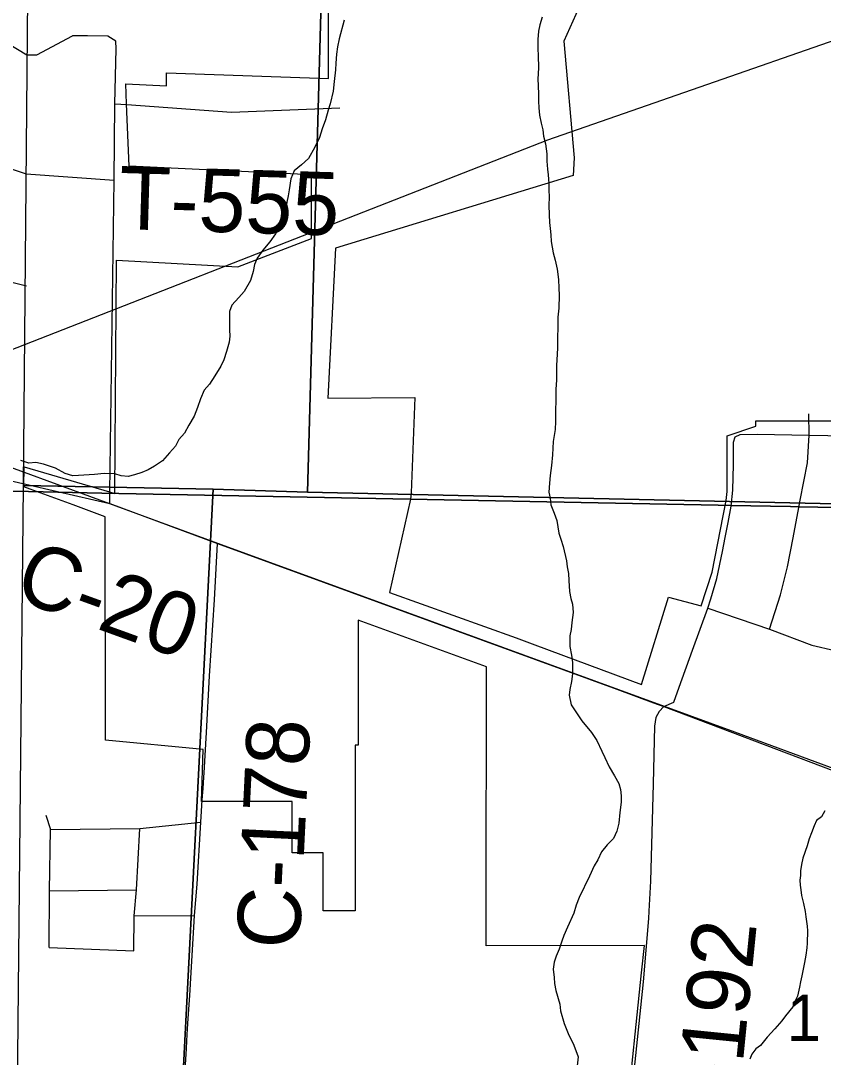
# Model space of a CAD drawing. Extents: x -8.5 to 18.7, y -20.3 to 7.
# Drawn here: x -2.808 to -1.362, y 0.088 to 1.955 of the extents above; entities that cross this region are included whole.
import ezdxf

# ---------------------------------------------------------------- set-up
doc = ezdxf.new("R2010")
doc.units = 0
for name, color, linetype in [('GM_X_City_Street', 7, 'Continuous'), ('GM_X_Corporation', 7, 'Continuous'), ('GM_X_County_Road', 7, 'Continuous'), ('GM_X_County_Road_Text', 7, 'Continuous'), ('GM_X_Minor_River', 7, 'Continuous'), ('GM_X_Rail_Line', 7, 'Continuous'), ('GM_X_Section', 7, 'Continuous'), ('GM_X_Section_Text', 7, 'Continuous'), ('GM_X_Township_Road', 7, 'Continuous'), ('GM_X_Township_Road_Text', 7, 'Continuous')]:
    doc.layers.add(name, color=color, linetype=linetype)

msp = doc.modelspace()

# ---------------------------------------------------------------- linework, layer by layer
at = {"layer": 'GM_X_City_Street'}
for points in [[(-3.9604, 2.6689), (-3.844, 2.5902), (-3.7175, 2.5047), (-3.6021, 2.4267), (-3.4745, 2.3404), (-3.4132, 2.299), (-3.3636, 2.2654), (-3.2476, 2.1868), (-3.1355, 2.111), (-2.9015, 1.9525), (-2.8514, 1.926), (-2.7975, 1.8934), (-2.779, 1.8934), (-2.7151, 1.9279)], [(-4.2496, 2.258), (-4.1287, 2.179), (-3.999, 2.0943), (-3.9351, 2.0526), (-3.8846, 2.0175), (-3.756, 1.928), (-3.6473, 1.8524), (-3.6362, 1.8446), (-3.5475, 1.7829), (-3.4907, 1.7508), (-3.4206, 1.7225), (-3.4109, 1.7186), (-3.2809, 1.6661), (-3.1664, 1.6197), (-3.0423, 1.5696), (-2.9414, 1.5288), (-2.937, 1.5266), (-2.8785, 1.4971), (-2.7977, 1.4775)], [(-1.717, -0.0221), (-1.6896, 0.2401), (-1.6844, 0.2891), (-1.9697, 0.2885), (-1.9697, 0.3478), (-1.9693, 0.7915), (-2.2001, 0.8752), (-2.2001, 0.6499), (-2.2058, 0.6499), (-2.2057, 0.3514), (-2.2632, 0.3514), (-2.2632, 0.4561), (-2.3191, 0.4561), (-2.3191, 0.5488), (-2.4824, 0.5488), (-2.4797, 0.6423), (-2.6553, 0.6589), (-2.6561, 1.0616), (-2.7137, 1.0832), (-2.7735, 1.1049), (-2.803, 1.1157), (-2.8022, 1.1518), (-2.6481, 1.1067), (-2.6387, 1.1034), (-2.636, 1.5237), (-2.4173, 1.5119), (-2.2847, 1.5629), (-2.2847, 1.6777), (-2.6131, 1.6929), (-2.6176, 1.8052), (-2.6192, 1.8412), (-2.5455, 1.838), (-2.5455, 1.8615), (-2.2535, 1.8513), (-2.2535, 2.0761)], [(-1.8029, 1.9786), (-1.8296, 1.9186), (-1.8111, 1.7083), (-1.8128, 1.6763), (-2.2411, 1.5453), (-2.2552, 1.2755), (-2.0985, 1.2767), (-2.1046, 1.1045), (-2.1063, 1.0933), (-2.144, 0.9251), (-1.9156, 0.8434), (-1.8821, 0.8308), (-1.6898, 0.7596), (-1.6411, 0.9167), (-1.5822, 0.9012), (-1.5625, 0.9617), (-1.5376, 1.091), (-1.5355, 1.107), (-1.5355, 1.2076), (-1.484, 1.2247), (-1.4838, 1.2346), (-1.4034, 1.2346), (-1.3485, 1.2346)], [(-2.9784, 1.7391), (-2.8676, 1.7022), (-2.856, 1.6983), (-2.7986, 1.6792)]]:
    msp.add_lwpolyline(points, dxfattribs=at)
at = {"layer": 'GM_X_Corporation'}
for points in [[(-1.3034, 1.0774), (-1.4067, 1.0795), (-1.4213, 1.0798), (-1.5287, 1.0819), (-1.5518, 1.0823), (-2.6619, 1.1042), (-2.7944, 1.1069), (-2.954, 1.11), (-3.2128, 1.1151), (-3.2551, 1.1159), (-3.3539, 1.1179), (-3.4465, 1.1197), (-3.6292, 1.1233), (-3.7871, 1.1264), (-3.9004, 1.1287), (-4.0993, 1.1326), (-4.6729, 1.1498)], [(-4.6729, 1.1498), (-4.0993, 1.1326), (-3.9004, 1.1287), (-3.7871, 1.1264), (-3.6292, 1.1233), (-3.4465, 1.1197), (-3.3539, 1.1179), (-3.2551, 1.1159), (-3.2128, 1.1151), (-2.954, 1.11), (-2.7944, 1.1069), (-2.6619, 1.1042), (-1.5518, 1.0823), (-1.5287, 1.0819), (-1.4213, 1.0798), (-1.4067, 1.0795), (-1.3034, 1.0774)]]:
    msp.add_lwpolyline(points, dxfattribs=at)
at = {"layer": 'GM_X_County_Road'}
for p, q in [((-2.7989, 1.1202), (-2.7422, 1.1073)), ((-2.4798, 0.5721), (-2.4784, 0.5924)), ((-2.4812, 0.5518), (-2.4798, 0.5721)), ((-2.4827, 0.5315), (-2.4812, 0.5518)), ((-2.4841, 0.5112), (-2.4827, 0.5315)), ((-2.4964, 0.3225), (-2.4953, 0.343)), ((-2.4988, 0.2814), (-2.4964, 0.3225)), ((-2.5012, 0.2404), (-2.4988, 0.2814))]:
    msp.add_line(p, q, dxfattribs=at)
for points in [[(-4.2631, 1.6441), (-3.9576, 1.5298), (-3.8324, 1.4829), (-3.6839, 1.4274), (-3.5358, 1.3719), (-3.4169, 1.3275), (-3.2907, 1.2802), (-3.1687, 1.2346), (-3.0663, 1.1994), (-2.9356, 1.1545), (-2.9102, 1.1457), (-2.7989, 1.1202)], [(-2.7422, 1.1073), (-2.6479, 1.0857), (-2.4539, 1.0135)], [(-2.4739, 0.6728), (-2.4684, 0.7751), (-2.4592, 0.9117), (-2.4539, 1.0135)], [(-2.4539, 1.0135), (-1.7343, 0.7509), (-1.6684, 0.7264)], [(-1.6496, 0.7195), (-1.658, 0.7105), (-1.6643, 0.7), (-1.6665, 0.6841), (-1.6687, 0.5806), (-1.6739, 0.4052), (-1.6764, 0.3511)], [(-1.6684, 0.7264), (-1.6496, 0.7195), (-1.3449, 0.6045)], [(-2.4784, 0.5924), (-2.4778, 0.6005), (-2.4739, 0.6728)], [(-2.4953, 0.343), (-2.4904, 0.3996), (-2.4841, 0.5112)], [(-1.6764, 0.3511), (-1.677, 0.3376), (-1.6866, 0.2239), (-1.7128, -0.024), (-1.724, -0.1375)], [(-2.5064, 0.1579), (-2.5036, 0.1994), (-2.5012, 0.2404)], [(-2.5088, 0.1174), (-2.5077, 0.1393), (-2.5064, 0.1579)], [(-2.5138, 0.0344), (-2.5118, 0.0647), (-2.5095, 0.1035), (-2.5088, 0.1174)]]:
    msp.add_lwpolyline(points, dxfattribs=at)
at = {"layer": 'GM_X_Minor_River'}
for points in [[(-1.8691, 1.9614), (-1.8731, 1.9478), (-1.8755, 1.9364), (-1.8764, 1.9212), (-1.8766, 1.9045), (-1.876, 1.8924), (-1.8755, 1.8703), (-1.8765, 1.8499), (-1.8759, 1.8385), (-1.8753, 1.8225), (-1.8754, 1.8104), (-1.8748, 1.7982), (-1.8734, 1.7853), (-1.8706, 1.7708), (-1.8677, 1.7586), (-1.8663, 1.7472), (-1.8626, 1.7335), (-1.8606, 1.7153), (-1.8607, 1.7024), (-1.8594, 1.688), (-1.858, 1.6773), (-1.8566, 1.6621), (-1.8567, 1.6507), (-1.8561, 1.6371), (-1.8571, 1.6226), (-1.8565, 1.6052), (-1.8559, 1.5915), (-1.8545, 1.5808), (-1.8531, 1.5694), (-1.8525, 1.5573), (-1.8489, 1.5368), (-1.8453, 1.5238), (-1.8417, 1.5078), (-1.8396, 1.4888), (-1.839, 1.4736), (-1.8384, 1.4607)], [(-2.2258, 1.9561), (-2.2345, 1.9228), (-2.2377, 1.9084), (-2.2394, 1.8947), (-2.2403, 1.8788), (-2.2412, 1.8667), (-2.2437, 1.8454), (-2.2454, 1.828), (-2.251, 1.8053), (-2.2542, 1.7939), (-2.2589, 1.7765), (-2.2652, 1.7606), (-2.2699, 1.7447), (-2.2785, 1.7274), (-2.2901, 1.707), (-2.3023, 1.6957), (-2.3154, 1.6845), (-2.3216, 1.6701), (-2.3249, 1.6504), (-2.3265, 1.6398), (-2.3289, 1.6284), (-2.3321, 1.6095), (-2.3353, 1.5959), (-2.3438, 1.5815), (-2.3493, 1.571), (-2.3593, 1.5566), (-2.3724, 1.5416), (-2.3824, 1.5273), (-2.3871, 1.5159), (-2.3895, 1.5031), (-2.3942, 1.4872), (-2.4058, 1.4675), (-2.4151, 1.4563), (-2.4281, 1.4427), (-2.432, 1.4314), (-2.4324, 1.398), (-2.4318, 1.3866), (-2.4327, 1.376), (-2.4374, 1.3593), (-2.4421, 1.3442), (-2.4476, 1.3328), (-2.4584, 1.3155), (-2.4684, 1.3004)], [(-1.8384, 1.4607), (-1.8387, 1.4372), (-1.8404, 1.4213), (-1.841, 1.3658), (-1.8419, 1.3545), (-1.8429, 1.334), (-1.8432, 1.3082), (-1.8442, 1.2907), (-1.8448, 1.233), (-1.8457, 1.2186), (-1.849, 1.1974), (-1.8499, 1.1852), (-1.85, 1.1731), (-1.8518, 1.1541), (-1.8543, 1.1359), (-1.8559, 1.1223), (-1.8569, 1.1056), (-1.8547, 1.095), (-1.8533, 1.0828), (-1.8474, 1.0683), (-1.8423, 1.0546), (-1.8388, 1.0318), (-1.8351, 1.0211), (-1.8307, 1.0081), (-1.8249, 0.9823), (-1.8235, 0.9716), (-1.8214, 0.9595), (-1.8208, 0.9465), (-1.8195, 0.9268), (-1.8173, 0.9146), (-1.8144, 0.904), (-1.8131, 0.8888), (-1.8155, 0.8713), (-1.8164, 0.8584), (-1.8189, 0.8471), (-1.8191, 0.8281), (-1.8162, 0.8121), (-1.8141, 0.7992), (-1.8143, 0.7787), (-1.816, 0.765), (-1.8192, 0.7506), (-1.8201, 0.74), (-1.8165, 0.7225), (-1.806, 0.7065), (-1.7971, 0.6942), (-1.7799, 0.6728), (-1.7702, 0.6583), (-1.7613, 0.6392), (-1.7561, 0.6277), (-1.7479, 0.6109), (-1.7383, 0.5949), (-1.7308, 0.5812), (-1.7279, 0.5705), (-1.7265, 0.5591), (-1.7267, 0.5477), (-1.7292, 0.5288), (-1.7309, 0.5098), (-1.7341, 0.4954), (-1.7403, 0.4818), (-1.7518, 0.4705), (-1.7618, 0.4577), (-1.7688, 0.4434), (-1.775, 0.4328), (-1.7836, 0.4139), (-1.8022, 0.3754), (-1.8077, 0.3618), (-1.8116, 0.3474), (-1.8233, 0.3225), (-1.8295, 0.3074), (-1.8335, 0.2968), (-1.8382, 0.2824), (-1.8436, 0.2703), (-1.8475, 0.259), (-1.8492, 0.2468), (-1.8471, 0.2316), (-1.8465, 0.221), (-1.8443, 0.2081), (-1.837, 0.1837), (-1.8356, 0.1715), (-1.8291, 0.1487), (-1.821, 0.1274), (-1.8128, 0.1128), (-1.8084, 0.0999), (-1.804, 0.0885), (-1.8057, 0.0725)], [(-2.4684, 1.3004), (-2.4777, 1.2899), (-2.4847, 1.274), (-2.4901, 1.2581), (-2.4956, 1.243), (-2.5057, 1.2264), (-2.5134, 1.2121), (-2.5234, 1.2008), (-2.5296, 1.1887), (-2.5404, 1.1767), (-2.5527, 1.1624), (-2.5672, 1.1527), (-2.5787, 1.146), (-2.5901, 1.1415), (-2.6031, 1.1371), (-2.6145, 1.1342), (-2.6274, 1.1351), (-2.6387, 1.139), (-2.6577, 1.1392), (-2.6751, 1.1379), (-2.704, 1.1359), (-2.7146, 1.1353), (-2.7282, 1.1392), (-2.7455, 1.1493), (-2.7675, 1.1563), (-2.7811, 1.1595), (-2.794, 1.1581), (-2.8084, 1.1628)], [(-1.3597, 0.5316), (-1.3658, 0.5211), (-1.3743, 0.5143), (-1.3789, 0.5045), (-1.3836, 0.4924), (-1.3875, 0.4811), (-1.3915, 0.469), (-1.3993, 0.4463), (-1.4017, 0.4349), (-1.4034, 0.4235), (-1.4035, 0.4152), (-1.4043, 0.4068), (-1.4037, 0.3977), (-1.403, 0.3894), (-1.4016, 0.3795), (-1.398, 0.365), (-1.3951, 0.3506), (-1.3937, 0.3407), (-1.3916, 0.324), (-1.3909, 0.3156), (-1.3912, 0.2936), (-1.3921, 0.2852), (-1.3937, 0.2716), (-1.3961, 0.2587), (-1.3994, 0.2436), (-1.401, 0.2345), (-1.4034, 0.2239), (-1.405, 0.214), (-1.409, 0.1981), (-1.4136, 0.1883), (-1.4175, 0.1785), (-1.4306, 0.1627), (-1.4368, 0.1536), (-1.4499, 0.1393), (-1.4637, 0.1243), (-1.4752, 0.1092), (-1.4836, 0.1033), (-1.4913, 0.0935), (-1.4945, 0.0844)]]:
    msp.add_lwpolyline(points, dxfattribs=at)
at = {"layer": 'GM_X_Rail_Line'}
for points in [[(-3.1051, 1.2532), (-1.8587, 1.7404), (-1.0506, 2.0219), (-0.5317, 2.1977), (0.6034, 2.6279), (1.0736, 2.8146), (2.4168, 3.2935), (3.3492, 3.6263), (4.4113, 3.9753)], [(-3.1051, 1.2532), (-2.4469, 1.0116), (-1.5221, 0.6739), (-0.4101, 0.2634), (0.7595, -0.1688), (1.8743, -0.5688), (3.1764, -1.0285), (4.3174, -1.4463), (6.1065, -2.1352), (6.899, -2.4421), (7.8038, -2.7637), (9.1245, -3.2289), (9.8265, -3.4832)]]:
    msp.add_lwpolyline(points, dxfattribs=at)
at = {"layer": 'GM_X_Section'}
for points in [[(-2.2369, 3.07), (-2.2915, 1.1056), (-2.4613, 1.1112), (-2.8031, 1.1178), (-2.7857, 3.0825)], [(-0.2637, 3.0843), (-0.2624, 3.0586), (-0.2815, 1.0613), (-2.2915, 1.1056), (-2.2369, 3.07)], [(-2.4613, 1.1112), (-2.5517, -0.6423), (-4.6445, -0.6408), (-4.6442, -0.2239), (-2.8166, -0.2124), (-2.8031, 1.1178)], [(-2.4613, 1.1112), (-2.2915, 1.1056), (-0.2815, 1.0613), (-0.3533, -0.74), (-0.3552, -0.7999), (-2.5517, -0.6423)]]:
    msp.add_lwpolyline(points, close=True, dxfattribs=at)
at = {"layer": 'GM_X_Township_Road'}
for p, q in [((-2.6385, 1.8057), (-2.6173, 1.8041)), ((-2.7986, 1.6792), (-2.6402, 1.6679)), ((-2.6479, 1.0857), (-2.6476, 1.1056)), ((-2.7563, 0.3879), (-2.5997, 0.3895)), ((-2.6038, 0.3429), (-2.4953, 0.343)), ((-2.7568, 0.2854), (-2.6048, 0.2799))]:
    msp.add_line(p, q, dxfattribs=at)
for points in [[(-2.6476, 1.1056), (-2.6402, 1.6679), (-2.6385, 1.8057), (-2.6361, 1.9044), (-2.6372, 1.9186), (-2.6514, 1.9276), (-2.6882, 1.9281), (-2.7151, 1.9279)], [(-2.6173, 1.8041), (-2.4283, 1.7903), (-2.2332, 1.7982)], [(-1.4063, 1.0784), (-1.4038, 1.0912), (-1.3907, 1.159), (-1.3879, 1.2087), (-1.3881, 1.2469)], [(-1.5391, 1.024), (-1.5337, 1.0512), (-1.5283, 1.0808), (-1.5251, 1.1093), (-1.5241, 1.1556), (-1.5239, 1.1962), (-1.5209, 1.2057)], [(-1.5209, 1.2057), (-1.5118, 1.2095), (-1.4817, 1.2101), (-1.3879, 1.2087), (-1.3543, 1.2081), (-1.3272, 1.2067), (-1.3043, 1.2008), (-1.2839, 1.1908), (-1.2679, 1.1787), (-1.2497, 1.1606)], [(-1.4595, 0.8591), (-1.4394, 0.9207), (-1.4271, 0.9712), (-1.4169, 1.0236), (-1.4063, 1.0784)], [(-1.6496, 0.7195), (-1.6319, 0.7276), (-1.622, 0.7545), (-1.5979, 0.8211), (-1.5706, 0.8967), (-1.5649, 0.9138), (-1.5541, 0.9502), (-1.5442, 0.9987), (-1.5391, 1.024)], [(-1.5706, 0.8967), (-1.4595, 0.8591), (-1.3831, 0.8304), (-1.3417, 0.8205), (-1.2946, 0.8171)], [(-2.7633, 0.5238), (-2.7546, 0.4983), (-2.5935, 0.5001), (-2.4841, 0.5112)], [(-2.7568, 0.2854), (-2.7563, 0.3879), (-2.7546, 0.4983)], [(-2.6048, 0.2799), (-2.6038, 0.3429), (-2.5997, 0.3895), (-2.5935, 0.5001)]]:
    msp.add_lwpolyline(points, dxfattribs=at)

# ---------------------------------------------------------------- texts
at = {"layer": 'GM_X_County_Road_Text'}
for s, rotation, p in [('C-20', 340.1025, (-2.8245, 0.9153)), ('C-178', 87.2485, (-2.3063, 0.2816)), ('C-192', 84.2806, (-1.5233, -0.0835))]:
    msp.add_text(s, height=0.11364, rotation=rotation, dxfattribs=at).set_placement(p)
at = {"layer": 'GM_X_Section_Text'}
msp.add_text('1', height=0.0837, rotation=0, dxfattribs=at).set_placement((-1.4285, 0.117))
at = {"layer": 'GM_X_Township_Road_Text'}
msp.add_text('T-555', height=0.11364, rotation=358.3152, dxfattribs=at).set_placement((-2.6326, 1.5799))

doc.saveas('drawing.dxf')
